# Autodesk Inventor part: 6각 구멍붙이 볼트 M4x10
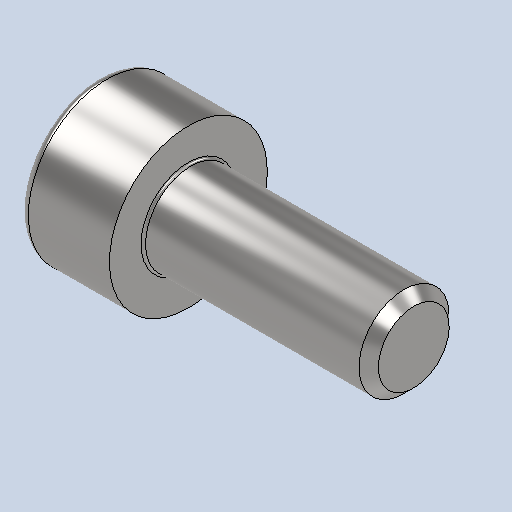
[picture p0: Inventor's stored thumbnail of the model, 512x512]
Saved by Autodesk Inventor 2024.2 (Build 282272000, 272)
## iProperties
Created: 2025-09
Part Number: 6각 구멍붙이 볼트 M4x10
Material: 강철, 연강
Description: 6각머리 태핑 나사
Document SubType Name: Modeling
Designer: home
Density: 7.85 g/cm^3
Appearance: 기본값
Author: jhkim
Sending System: Autodesk Inventor 2026
Preprocessor: ST-DEVELOPER v20.1
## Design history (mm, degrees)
feature "Solid1"
node "솔리드1"
